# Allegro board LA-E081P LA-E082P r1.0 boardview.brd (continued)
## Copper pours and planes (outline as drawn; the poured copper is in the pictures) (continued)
SNUB_1.8VALW on TOP (solid shape): 126.37,106.75 126.37,105.13 126.29,105.05 125.37,105.05 125.29,105.12 125.29,105.79 125.73,106.22 125.73,106.77 125.78,106.82 126.3,106.82
SNUB_1V_PRIM on TOP (solid shape): 127.36,110.36 127.36,109.87 127.8,109.44 127.8,108.81 127.68,108.69 126.84,108.69 126.66,108.87 126.66,110.38 126.72,110.44 127.28,110.44
SNUB_1VS_VCCIO on TOP (solid shape): 137.73,108.02 137.73,107.29 137.9,107.12 138.54,107.12 138.65,107.01 138.65,106.39 138.58,106.32 137.15,106.32 137.03,106.45 137.03,108.01 137.12,108.1 137.65,108.1
SNUB_CHG1 on TOP (solid shape): 19.78,26.55 19.78,24.8 19.36,24.38 17.34,24.38 17.02,24.7 17.02,24.71 17.11,24.95 17.02,25.19 17.02,26.05 17.11,26.28 17.03,26.51 17.2,26.68 19.65,26.68
SNUB_CHG2 on TOP (solid shape): 32.55,20.84 32.55,18.82 32.29,18.56 31.25,18.56 30.92,18.88 30.92,19.35 29.98,20.29 29.98,20.95 30.07,21.04 32.35,21.04
SW1_ISL88738 on TOP (solid shape): 23.04,27.47 23.04,24.95 22.6,24.51 20.82,24.51 20.44,24.9 20.44,27.58 20.77,27.91 22.6,27.91
SW1_ISL88738 on BOTTOM (solid shape): 23.31,27.64 23.31,22.75 23.06,22.5 19.18,22.5 18.86,22.81 18.86,23.77 18.55,24.08 17.59,24.08 17.4,24.28 17.4,27.89 17.47,27.96 22.99,27.96
SW2_ISL88738 on TOP (solid shape): 32.69,23.61 32.69,22.04 32.34,21.68 29.82,21.68 29.57,21.94 29.57,23.82 29.8,24.05 32.26,24.05
SW2_ISL88738 on BOTTOM (solid shape): 32.9,26.69 32.9,18.75 32.52,18.37 28.71,18.37 28.45,18.62 28.45,26.62 28.83,27.01 32.58,27.01
SW_+1VALWP on BOTTOM (solid shape): 180.35,96.79 180.35,95.55 180.29,95.5 180.14,95.5 179.46,96.18 179.46,96.6 179.84,96.98 180.15,96.98
SW_+1VALWP on BOTTOM (solid shape): 180.79,93.17 180.79,91.78 181.36,91.2 182.31,91.2 182.31,88.98 182.25,88.92 177.04,88.92 176.73,89.24 176.73,91.14 176.92,91.14 176.92,91.15 177.31,91.15 177.55,91.38 177.55,91.77 177.55,91.78 177.55,92.41 178.76,92.41 179.33,92.98 179.84,92.98 180.12,93.26 180.7,93.26
UG1_ISL88738 on TOP (solid shape): 19.44,20.78 19.44,20.25 19.43,20.24 19.4,20.11 19.41,19.97 19.42,19.95 19.18,19.7 19.18,18.75 19.12,18.69 18.99,18.69 18.93,18.75 18.93,19.96 18.86,20.02 18.86,20.78 18.99,20.91 19.31,20.91
UG1_ISL88738 on BOTTOM (solid shape): 12.96,27.83 12.96,27.32 12.9,27.26 10.93,27.26 10.86,27.32 10.86,27.89 10.93,27.96 11.49,27.96 12.83,27.96
UG2_ISL88738 on TOP (solid shape): 22.38,17.27 22.38,17.24 22.39,17.24 22.39,16.94 22.29,16.85 21.53,16.85 21.34,17.04 20.13,17.04 20.07,17.1 20.07,17.23 20.13,17.29 21.08,17.29 21.15,17.29 21.21,17.35 22.29,17.35
UG2_ISL88738 on BOTTOM (solid shape): 29.62,13.67 29.62,12.55 29.5,12.43 28.56,12.43 28.47,12.52 28.47,13.62 28.71,13.86 29.43,13.86
N16399089 on TOP (solid shape): 9.25,24.53 9.81,24.53 9.94,24.66 11.73,24.66 12.12,24.26 12.12,21.35 11.9,21.13 8.58,21.13 7.4,22.3 7.4,24.18 7.52,24.3 8.15,24.3 8.5,24.66 9.12,24.66
N16783126 on TOP (solid shape): 153.32,110.86 154.18,110.86 154.41,111.09 155.07,111.09 155.15,111.02 155.15,109.09 154.59,108.53 153.9,108.53 153.5,108.93 153.5,109.57 153.24,109.82 152.36,109.82 152.28,109.9 152.28,111.4 152.35,111.47 152.71,111.47
N17370862 on TOP (solid shape): 48.39,82.82 48.39,81.81 48.9,81.3 48.9,80.03 48.14,79.27 47.78,79.27 47.61,79.43 47.38,79.49 47.38,82.82 47.5,82.95 48.27,82.95
N17371029 on TOP (solid shape): 49.37,92.77 49.37,90.68 48.96,90.27 48.56,90.27 48.25,89.96 48.25,89.35 48.03,89.13 47.55,89.13 47.5,89.18 47.45,89.18 47.21,89.42 47.21,91.96 47.36,92.25 47.21,92.54 47.21,92.71 47.57,93.07 49.08,93.07
N18762349 on TOP (solid shape): 306.46,33.8 306.96,33.8 307.15,33.61 307.15,32.03 307.15,31.9 307.03,31.77 306.58,31.77 306.33,32.02 306.33,32.72 306.27,32.78 306.27,33.23 305.69,33.8 302.33,33.8 302.27,33.86 302.27,33.99 302.33,34.05 306.2,34.05
N18762426 on TOP (solid shape): 307.07,34.6 307.07,34.05 307.03,34 306.46,34 306.31,34.15 306.28,34.15 306.25,34.18 302.28,34.18 302.25,34.15 302.21,34.15 302.15,34.22 302.15,34.46 302.21,34.51 302.27,34.5 302.31,34.49 304.51,34.49 304.53,34.52 306.22,34.52 306.41,34.7 306.97,34.7
N27076242 on TOP (solid shape): 21.68,23.79 21.68,22.68 21.64,22.64 19.04,22.64 18.91,22.77 18.91,23.85 18.97,23.92 21.55,23.92
N32818355 on TOP (solid shape): 200.49,8.88 200.49,8.45 200.83,8.11 202.21,8.11 202.29,8.02 202.29,7.93 202.26,7.86 202.18,7.83 202.14,7.84 201.05,7.84 200.99,7.77 200.9,7.77 200.57,7.45 199.85,7.45 199.79,7.52 199.79,8.96 199.88,9.06 199.97,9.05 200.07,9.07 200.31,9.07
N35551558 on TOP (solid shape): 15.52,52.82 16.16,52.82 16.41,52.57 16.41,50.26 16.26,50.11 14.69,50.11 14.61,50.18 14.61,51.66 14.43,51.83 14.43,51.96 14.31,52.09 14.31,52.72 14.43,52.85 15.52,52.85
N35551576 on TOP (solid shape): 19.88,56.11 19.88,54.5 19.25,53.87 18.51,53.87 18.29,54.09 18.29,56.21 18.4,56.32 19.66,56.32
N35551584 on TOP (solid shape): 67.99,106.68 67.99,105.11 68.06,105.04 68.06,103.82 67.88,103.64 66.27,103.64 65.96,103.95 65.96,105.76 67.12,106.91 67.75,106.91
N35551584 on BOTTOM (solid shape): 71.11,105.33 71.11,104.13 70.89,103.91 70.04,103.91 69.64,104.31 69.64,104.34 69.61,104.34 69.44,104.51 69.44,104.92 69.67,105.15 69.72,105.15 70.01,105.44 71,105.44
N35551696 on TOP (solid shape): 4.77,51.01 9.99,51.01 10.14,50.86 10.55,50.86 10.67,50.73 10.67,50.18 10.55,50.06 4.13,50.06 3.88,49.8 3.88,49.1 3.37,49.1 3.37,50.25 3.12,50.5 3.12,51.58 3.43,51.9 3.88,51.9
N35551783 on TOP (solid shape): 10.55,44.29 10.55,43.45 10.93,43.07 10.93,40.53 10.67,40.28 10.04,40.28 9.28,39.52 7.5,39.52 7.12,39.9 7.12,40.53 7.75,41.17 9.66,41.17 9.78,41.29 9.78,42.94 9.74,42.98 9.74,44.3 9.83,44.39 10.44,44.39
N36626863 on BOTTOM (solid shape): 41.64,100.99 41.64,100.46 41.4,100.22 40.72,100.22 40.7,100.25 40.22,100.25 40.05,100.42 38.31,100.42 38.17,100.56 38.17,101.08 38.27,101.18 41.46,101.18
N36827741 on TOP (solid shape): 128.35,30.57 128.95,30.57 129.25,30.28 129.25,29.62 129.36,29.5 129.36,28.58 129.2,28.42 128.71,28.42 128.58,28.55 128.58,28.93 128.7,29.05 128.7,29.41 128.31,29.8 127.57,29.8 127.45,29.68 126.95,29.68 126.85,29.77 126.85,30.47 127.16,30.77 128.15,30.77
N45912878 on BOTTOM (solid shape): 170.13,112.08 170.95,112.08 170.95,111.21 169.51,111.21 168,112.72 168,113.43 168.1,113.53 168.69,113.53
N46204184 on BOTTOM (solid shape): 182.12,93.21 182.12,93.11 184.09,91.14 184.6,91.14 184.6,90.25 183.77,90.25 181.93,92.09 181.62,92.09 181.42,92.28 181.42,93.2 181.49,93.26 182.07,93.26
N132000604 on TOP (solid shape): 24.71,18.18 24.71,16.21 24.58,16.08 24.01,16.08 23.88,16.21 23.88,18.24 24.01,18.37 24.52,18.37

Small or netless copper shapes (teardrops, artwork), in the pictures only: 112 on TOP, 25 on BOTTOM

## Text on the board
Ref Des/Silkscreen Bottom: M2X3 | H38 | REV:A00 | PWB:TXD2X | ALL RIGHT RESERVED | COPYRIGHT 2016
User.Comments: LA-E081P | Saijuan | 2016-11-07 | 2017-11-07 | CDM70
BODY_CENTER: L7 | L8 | L9 | L10 | IN2 | IN3 | VCC | IN4
User.45: trace wide | wide/space | SB_1_2mm-10L(4mil 50ohm)_WithOutC_151106.pdf | L2-GND1 | L3-IN1 | L4-GND2 | L1-TOP | L5-IN2 | L6-IN3 | L7-VCC | L8-IN4 | L9-GND3 | L10-BOT | LAYER | NAME | STACKUP: 10 LAYER | 39 ohm | 5.6 | 6.6 | 50 ohm | 4.8 | 3.5 | 4 | THICKNESS=1.2mm | 83 ohm | 3.9/3.5 | 3.6/3.5 | 3.5/3.6 | 4.8/4.3 | 3.7/3.6 | 85 ohm | 3.7/4.7 | 3.5/4.9 | 90 ohm | 100 ohm | 3.5/8.3 | 3/6.5 | FIGURE | SIZE | 8.0 | 10.0 | 20.0 | 28.0 | 35.0 | 39.0 | 87.0 | 91.0 | 98.0 | 118.0 | 126.0 | 150.0 | 157.0 | 31.0 | 40.0 | 43.0 | 63.0 | 71.0 | 49.0x28.0 | 55.0x24.0 | 59.0x28.0 | 67.0x31.0 | 71.0x28.0 | 71.0x31.0 | 75.0x24.0 | 79.0x31.0 | 94.0x28.0 | 100.0x31.0 | 102.0x31.0 | 142.0x102.0 | DRILL CHART: TOP to BOTTOM | ALL UNITS ARE IN MILS | TOLERANCE | +3.0/-3.0 | +2.0/-2.0 | PLATED | NON-PLATED | QTY | 6178 | 1 | 19 | 42 | 10 | 5 | 3 | 6 | 2 | 8 | 7
